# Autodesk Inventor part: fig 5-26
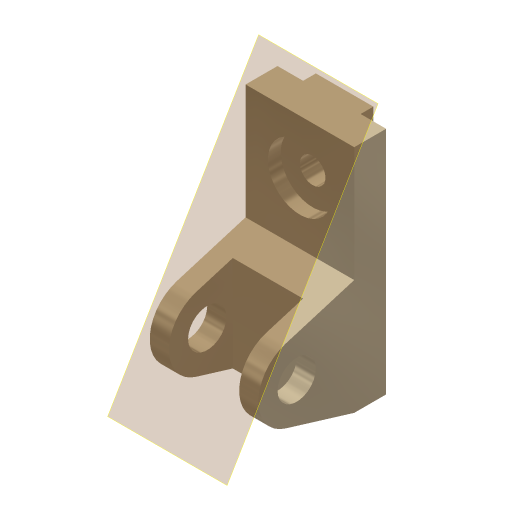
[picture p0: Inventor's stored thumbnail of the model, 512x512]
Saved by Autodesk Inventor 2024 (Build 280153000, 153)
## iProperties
Shininess: 65.0
Angle Display Precision: 2
Document Length Units: 11269
Document Angle Units: 11279
Document Time Units: 11290
Document Mass Units: 11283
Document Length Units Precision: 3
Document Angle Units Precision: 2
Compacted: False
Created: 2001-11
Part Number: fig 5-26
Document SubType Name: Modeling
Designer: Renu Muthoo
Density: 1 g/cm^3
Material: Generic
Appearance: Metal-Titanium (Polished)
Density: 0.0
Volumn: 0.0
Area: 0.0
PropertySet Name: Model Information
Control State: 0
Master: False
Checked Out: False
Author: Renu Muthoo
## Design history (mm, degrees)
sketch "Sketch2"
  geometry: L1 (33.257, 104.664)-(33.257, -75.336); L2 (33.257, -75.336)-(8.257, -75.336); L3 (8.257, -75.336)-(-45.451, -59.045); L4 (-45.451, -1.628)-(8.257, 14.664); L5 (8.257, 14.664)-(8.257, 104.664); L6 (8.257, 104.664)-(33.257, 104.664); C1 r 15 at (-36.743, -30.336); A1 r 30 centre (-36.743, -30.336) between (-45.451, -1.628) and (-45.451, -59.045)
  constraints: 12 end point, 2 centre point, 2 equal length, 2 parallel, 2 point on circle, 2 tangent, 1 coincident, 1 perpendicular, 1 vertical
  dimensions: "d0" = 180 distance of L1.start L1.end; "d1" = 30 radius of A1; "d2" = 25 distance of L5.end L1.start; "d3" = 45 distance from line of L2 A1.centre; "d4" = 70 distance from line of L1 A1.centre; "d5" = 30 diameter of C1
extrude "Extrusion1" new body sketch "Sketch2" distance "d6" = 85; taper "d7" = 0 deg
workplane "Work Plane1"
sketch "Sketch3"
  geometry: L1 (15, 62.364)-(70, 62.364); L2 (70, 62.364)-(70, -52.386); L3 (70, -52.386)-(15, -52.386); L4 (15, -52.386)-(15, 62.364); L5 (0, -45)-(0, -28.708) reference
  constraints: 8 end point, 2 parallel, 1 horizontal, 1 perpendicular
  dimensions: "d8" = 55 distance of L1.start L1.end; "d9" = 15 distance between parallel lines of L5 L4
extrude "Extrusion2" cut sketch "Sketch3" distance "d10" = 50; taper "d11" = 0 deg
sketch "Sketch4"
  geometry: L1 (0, 25)-(85, 25) reference; L2 (0, 0)-(0, 25) reference; L3 (20, 25)-(65, 25); L4 (65, 25)-(65, 35); L5 (65, 35)-(20, 35); L6 (20, 35)-(20, 25)
  constraints: 8 end point, 2 parallel, 1 horizontal, 1 perpendicular, 1 point on line
  dimensions: "d12" = 45 distance of L4.end L5.end; "d13" = 10 distance of L3.end L4.end; "d14" = 20 distance between parallel lines of L2 L6
extrude "Extrusion3" join sketch "Sketch4" stored distance "d15" = 50; taper "d16" = 0 deg
sketch "Sketch5"
  geometry: L1 (85, 0)-(85, 90) reference; L2 (0, 90)-(85, 90) reference; 1 further point
  dimensions: "d17" = 42 distance from line of L2 point (42.5, 48); "d18" = 42.5 distance from line of L1 point (42.5, 48)
hole "Hole1" sketch "Sketch5" diameter "d19" = 20; stored, may be unused: countersink angle "d23" = 82 deg, drill point angle "d25" = 118 deg; dims "d20" = 6, "d21" = 50, "d22" = 10, "d24" = 8
workplane "Work Plane12"
body "Solid1"
node "Sketch1"
